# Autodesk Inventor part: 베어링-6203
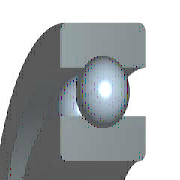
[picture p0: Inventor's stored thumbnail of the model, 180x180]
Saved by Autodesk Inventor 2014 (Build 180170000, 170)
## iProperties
IsCustomPart: 0
Created: 2016-05
Part Number: 베어링-6203
Material: 강, 연강
Description: 깊은 그루브 볼 베어링
Document SubType Name: Modeling
Standard: KS B 2023
Designer: mduedu
Standards Organization: KS
Language: ko-KR
Size Designation: 6203 - 17 x 40 x 12
Categories: <MemberInstance><Categories><Category DisplayName="샤프트 부품" InternalName="7f7aeb1f-a693-4053-b835-cee3144e0d98" Mnemonic="SHFT"><Category DisplayName="베어링" Inter
Density: 1 g/cm^3
Appearance: Yellow
Author: mduedu
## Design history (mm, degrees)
sketch "스케치" dims "d0" = 5.98 (= -0.26 x WD + 0.26 x BD)
  geometry: L1 (3.01, 14.25)-(8.99, 14.25); L2 (6, 14.25)-(6, 11.26); L3 (6, 14.25)-(6, 17.24); L4 (3.778, 12.249)-(0, 12.249); L5 (0, 8.5)-(12, 8.5); L6 (3.778, 16.251)-(0, 16.251); L7 (0, 20)-(12, 20); L8 (12, 8.5)-(12, 12.249); L9 (8.222, 12.249)-(12, 12.249); L10 (8.222, 16.251)-(12, 16.251); L11 (12, 20)-(12, 16.251); L12 (-1.4, 0)-(8.4, 0) reference; L13 (0, -0.3)-(0, 5.3) reference
  constraints: 22 end point, 4 point on line, 2 collinear, 2 perpendicular, 2 symmetric about line, 1 midpoint, 1 parallel, 14 other
  dimensions: "d9" = 17 diameter of L5 L12 (= WD); "d11" = 40 diameter of L7 L12 (= BD); "d12" = 12 distance between parallel lines of L8 L13 (= KB); "d13" = 24.498 diameter of L9 L12 (= 0.326 x BD + 0.674 x WD)
revolve "본체" stored, may be unused: angle "d6" = 90 deg
revolve "볼" stored, may be unused: angle "d7" = 90 deg
pattern_circular "IDS_ARRAYBALL[SIMPL:T]" dims angle "d3" = 360 deg
body "Solid1"
fillet "모깎기1" dims "d1" = 0.6 (= KRS)
other parameters: "WD" = 17 [user parameter; used in 5 equation terms], "BD" = 40 [user parameter; used in 5 equation terms], "KB" = 12 [user parameter; used in 1 equation term], "KRS" = 0.6 [user parameter; used in 1 equation term], "d4" = 0, "d5" = 0, "d8" = 0, "d14" = 0, "d15" = 0, "BBA" = 0 [user parameter], "BC0" = 4750000 [user parameter], "BC" = 9560000 [user parameter], "WR" = 8.5 (= 0.5 x WD) [user parameter]
